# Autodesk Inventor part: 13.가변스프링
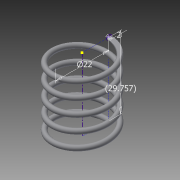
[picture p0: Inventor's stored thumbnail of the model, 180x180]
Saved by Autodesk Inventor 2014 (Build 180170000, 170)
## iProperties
Created: 2016-01
Part Number: 13.가변스프링
Material: Generic
Document SubType Name: Modeling
Designer: Administrator
Density: 1 g/cm^3
Appearance: Default
Author: Administrator
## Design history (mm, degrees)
sketch "스케치1"
  geometry: L1 (0, -29.757)-(11, -29.757); L2 (11, -29.757)-(11, 0); L3 (11, 0)-(0, 0); L4 (0, 0)-(0, -29.757); C1 r 1 at (11, 0); 1 further point
  constraints: 8 end point, 2 coincident, 2 parallel, 1 centre point, 1 horizontal, 1 perpendicular
  dimensions: "d0" = 2 diameter of C1; "d1" = 22 diameter of L2 L4; "d2" = 29.75741 distance of L1.end L2.end (derived)
feature "코일1" pitch "d3" = 10; turns "d5" = 5; dims "d4" = 29.75741 (= d2), "d6" = 0, angle "d7" = 90 deg, angle "d8" = 90 deg, "d9" = 0, "d10" = 0
sketch "스케치4"
  geometry: L1 (0, 10)-(0, 12) reference; 1 further point
  constraints: 1 vertical alignment
extrude "돌출3" cut sketch "스케치4" distance "d16" = 10; taper "d17" = 0 deg
node "작업 평면2"
sketch "스케치5"
  geometry: L1 (12, 0)-(10, 0) reference; 1 further point
  constraints: 1 horizontal alignment
extrude "돌출4" cut sketch "스케치5" distance "d19" = 10; taper "d20" = 0 deg
node "솔리드1"
node "절단 모서리 투영3"
node "절단 모서리 투영4"
other parameters: "d18" = 0
